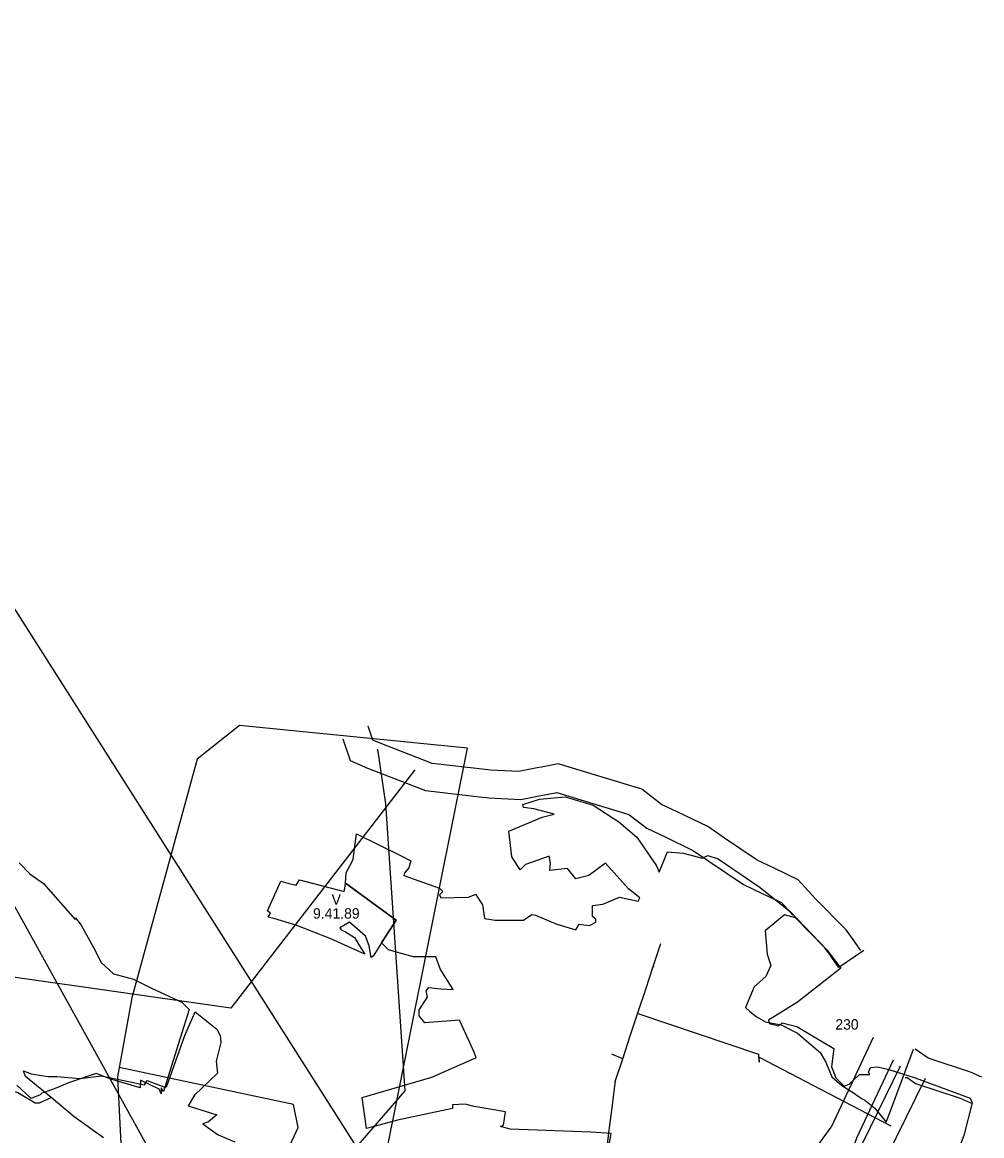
# Model space of a CAD drawing. Extents: x -694504 to -690518, y -983661 to -978958.
# Drawn here: x -691897 to -690518, y -980583 to -978982 of the extents above; entities that cross this region are included whole.
import ezdxf

# ---------------------------------------------------------------- set-up
doc = ezdxf.new("R2010")
doc.units = 0
for name, color, linetype in [('bezpečnostní pásmo', 7, 'Continuous'), ('BPEJ', 7, 'Continuous'), ('chráněné ložiskové území', 7, 'Continuous'), ('lokální biocentra', 7, 'Continuous'), ('nadregionální biokoridor', 7, 'Continuous'), ('Natura 2000', 7, 'Continuous'), ('ochranné pásmo dálkového kabelu', 7, 'Continuous'), ('ochranné pásmo radioreleové trasy', 7, 'Continuous'), ('OP vodního zdroje 2 stupně', 7, 'Continuous'), ('třídy přednosti v ochraně ZP', 7, 'Continuous'), ('vedení NN', 7, 'Continuous'), ('VTL plynovod', 7, 'Continuous')]:
    doc.layers.add(name, color=color, linetype=linetype)

msp = doc.modelspace()

# ---------------------------------------------------------------- linework, layer by layer
at = {"layer": 'bezpečnostní pásmo'}
for points in [[(-690673.7, -980441.7), (-690734.3, -980570.8), (-690734.4, -980570.8), (-691030.9, -980978.4), (-691232.9, -981356.8), (-691374.8, -981727), (-691755.3, -981882.6), (-691867.9, -982087.1), (-691866.5, -982152.1)], [(-691698.8, -981974.2), (-691698.8, -981974.2), (-691689.8, -981958.1), (-691300.2, -981796), (-691146.3, -981397.9), (-690951.9, -981030.3), (-690689.1, -980666.7), (-690682.1, -980670.7), (-690598.6, -980500.1)]]:
    msp.add_lwpolyline(points, dxfattribs=at)
at = {"layer": 'BPEJ'}
for points in [[(-691235.4, -980250.8), (-691232.4, -980270.8), (-691217.4, -980272.8), (-691176.4, -980272.8), (-691164.4, -980264.8), (-691159.4, -980265.8), (-691128.4, -980278.8), (-691101.4, -980286.8), (-691096.4, -980278.8), (-691081.4, -980280.8), (-691072.4, -980275.8), (-691072.4, -980271.8), (-691077.4, -980267.8), (-691077.4, -980251.8), (-691062.4, -980249.8), (-691038.4, -980239.8), (-691011.4, -980245.8), (-691009.4, -980240.8), (-691025.4, -980227.8), (-691058.4, -980190.8), (-691082.4, -980208.8), (-691101.4, -980213.8), (-691113.4, -980198.8), (-691138.4, -980201.8), (-691137.4, -980190.8), (-691139.4, -980180.8), (-691173.4, -980192.8), (-691181.4, -980200.8), (-691193.4, -980181.8), (-691197.4, -980144.8), (-691149.4, -980124.8), (-691132.4, -980120.8), (-691161.4, -980112.8), (-691176.4, -980110.8), (-691177.4, -980106.8), (-691153.4, -980098.8), (-691116.4, -980095.8), (-691076.4, -980107.8), (-691039.4, -980131.8), (-691013.4, -980153.8), (-690985.4, -980194.8), (-690981.4, -980203.8), (-690969.4, -980174.8), (-690946.4, -980176.8), (-690919.4, -980183.8), (-690911.4, -980179.8), (-690896.4, -980184.8), (-690836.4, -980225.8), (-690792.4, -980260.8), (-690740.4, -980315.8), (-690720.4, -980341.8), (-690782.4, -980390.8), (-690824.4, -980416.8), (-690823.4, -980421.8), (-690809.4, -980424.8), (-690804.4, -980420.8), (-690783.4, -980425.8), (-690730.4, -980457.8), (-690733.4, -980483.8), (-690727.4, -980499.8), (-690715.4, -980511.8), (-690708.4, -980508.8), (-690693.4, -980494.8), (-690678.4, -980494.8), (-690680.4, -980491.8), (-690677.4, -980484.8), (-690667.4, -980483.8), (-690651.4, -980487.8), (-690613.4, -980499.8), (-690534.4, -980528.8), (-690531.4, -980535.8), (-690543.4, -980582.8), (-690589.4, -980703.8)], [(-691055.4, -980605.8), (-691050.4, -980579.8), (-691079.4, -980577.8), (-691195.4, -980573.8), (-691209.4, -980569.8), (-691205.4, -980567.8), (-691202.4, -980548.8), (-691247.4, -980540.8), (-691260.4, -980537.8), (-691278.4, -980538.8), (-691278.4, -980543.8), (-691357.4, -980560.8), (-691402.4, -980572.8), (-691408.4, -980527.8), (-691308.4, -980498.8), (-691247.4, -980471.8), (-691244.4, -980470.8), (-691247.4, -980462.8), (-691268.4, -980416.8), (-691318.4, -980420.8), (-691326.4, -980410.8), (-691326.4, -980401.8), (-691314.4, -980383.8), (-691316.4, -980374.8), (-691312.4, -980369.8), (-691295.4, -980371.8), (-691277.4, -980372.8), (-691296.4, -980342.8), (-691302.4, -980325.8), (-691334.4, -980325.8), (-691352.4, -980320.8), (-691370.4, -980315.8), (-691375.4, -980310.8), (-691380.4, -980305.8), (-691359.4, -980272.8), (-691432.4, -980219.8), (-691431.4, -980204.8), (-691421.4, -980185.8), (-691420.4, -980177.8), (-691416.4, -980148.8), (-691353.4, -980179.8), (-691338.4, -980187.8), (-691341.4, -980197.8), (-691347.4, -980204.8), (-691348.4, -980208.8), (-691297.4, -980226.8), (-691292.4, -980231.8), (-691297.4, -980236.8), (-691295.4, -980240.8), (-691255.4, -980239.8), (-691247.4, -980236.8), (-691245.4, -980235.8), (-691235.4, -980250.8)], [(-691780.4, -980585.8), (-691822.4, -980555.8), (-691855.4, -980527.8), (-691892.4, -980497.8), (-691895.4, -980489.8), (-691884.4, -980493.8), (-691860.4, -980497.8), (-691847.4, -980497.8), (-691814.4, -980500.8), (-691783.4, -980496.8), (-691721.4, -980509.8), (-691717.4, -980503.8), (-691691.4, -980513.8), (-691689.4, -980511.8), (-691663.4, -980438.8), (-691648.4, -980404.8), (-691617.4, -980429.8), (-691612.4, -980438.8), (-691611.4, -980448.8), (-691618.4, -980475.8), (-691616.4, -980492.8), (-691649.4, -980524.8), (-691658.4, -980539.8), (-691617.4, -980552.8), (-691629.4, -980562.8)], [(-691944.4, -980516.8), (-691920.4, -980515.8), (-691903.4, -980520.8), (-691878.4, -980535.8), (-691872.4, -980535.8), (-691855.4, -980527.8)], [(-691629.4, -980562.8), (-691637.4, -980565.8), (-691615.4, -980581.8), (-691591.4, -980591.8)]]:
    msp.add_lwpolyline(points, dxfattribs=at)
msp.add_lwpolyline([(-691432.4, -980219.8), (-691359.4, -980272.8), (-691380.4, -980305.8), (-691392.4, -980324.8), (-691395.4, -980326.8), (-691398.4, -980309.8), (-691403.4, -980295.8), (-691426.4, -980275.8), (-691440.4, -980283.8), (-691438.4, -980286.8), (-691432.4, -980289.8), (-691419.4, -980297.8), (-691412.4, -980309.8), (-691404.4, -980321.8), (-691453.4, -980299.8), (-691502.4, -980280.8), (-691535.4, -980270.8), (-691543.4, -980268.8), (-691540.4, -980262.8), (-691544.4, -980259.8), (-691525.4, -980216.8), (-691515.4, -980219.8), (-691503.4, -980222.8), (-691498.4, -980214.8), (-691434.4, -980231.8), (-691433.4, -980226.8), (-691432.4, -980219.8)], close=True, dxfattribs=at)
at = {"layer": 'chráněné ložiskové území'}
msp.add_lwpolyline([(-691332.6, -980056.6), (-691597, -980399.4), (-692068.6, -980332.4), (-692715.6, -979056.8)], dxfattribs=at)
at = {"layer": 'lokální biocentra'}
msp.add_lwpolyline([(-690687.3, -980316.4), (-690722.9, -980340.9), (-690732, -980328.2), (-690735, -980324), (-690743.1, -980312.7), (-690785.6, -980269.6), (-690801, -980265.4), (-690829, -980288.2), (-690826.1, -980322), (-690820.6, -980338.1), (-690828, -980354), (-690844.6, -980369), (-690857.1, -980398.6), (-690851, -980404.2), (-690842.1, -980411.4), (-690828.4, -980419.1), (-690805.8, -980423.4), (-690782.6, -980435.7), (-690749.7, -980463.2), (-690741.6, -980477.1), (-690733.1, -980498.1), (-690718.9, -980510.8), (-690701.9, -980521.4), (-690693.6, -980527.1), (-690689.4, -980530.1), (-690685.6, -980531.9), (-690671.1, -980543.5), (-690655, -980563.5), (-690649, -980547.3), (-690615.9, -980458.4)], dxfattribs=at)
at = {"layer": 'nadregionální biokoridor'}
for points in [[(-690691.3, -980316.4), (-690699.5, -980304.9), (-690702.5, -980300.8), (-690712.4, -980286.9), (-690756.5, -980242.1), (-690781.4, -980214.8), (-690816.1, -980198.4), (-690840.5, -980186.8), (-690887.5, -980155.2), (-690911.5, -980138.4), (-690955.7, -980117.3), (-690978.2, -980106.5), (-691006.2, -980084.8), (-691126.6, -980048.1), (-691150.8, -980052.9), (-691156.9, -980054), (-691183.3, -980059.2), (-691223.9, -980057.1), (-691231.5, -980056.5), (-691307.8, -980047.5), (-691382.6, -980018.7), (-691393.3, -980014.2), (-691399.9, -979994)], [(-691436, -980012.2), (-691425.8, -980043.5), (-691400.9, -980054.5), (-691397, -980056), (-691317.4, -980086.7), (-691235.4, -980096.3), (-691229.6, -980096.8), (-691226.5, -980097), (-691180.5, -980099.4), (-691149.2, -980093.3), (-691143.2, -980092.1), (-691128.7, -980089.3), (-691024.9, -980120.9), (-690999.3, -980140.8), (-690973, -980153.3), (-690931.8, -980173.1), (-690910.1, -980188.2), (-690860.3, -980221.6), (-690833.2, -980234.5), (-690805.7, -980247.6), (-690789, -980265.9)], [(-690517.6, -980499), (-690533.9, -980491.5), (-690594.7, -980471.7), (-690613.2, -980458.5)], [(-690627.7, -980499.4), (-690625, -980499.2), (-690612.9, -980507.8), (-690548.6, -980528.8), (-690531.3, -980536.8)]]:
    msp.add_lwpolyline(points, dxfattribs=at)
at = {"layer": 'Natura 2000'}
msp.add_lwpolyline([(-691901.8, -980190.6), (-691886.4, -980206.2), (-691866.8, -980220.1), (-691821.1, -980272), (-691820.6, -980269.5), (-691812.4, -980280.1), (-691794.5, -980312.2), (-691783.5, -980333.8), (-691765.7, -980350.2), (-691737.2, -980357.9), (-691711.1, -980370.8), (-691700, -980376), (-691698, -980376.9), (-691667.9, -980390.9), (-691657.2, -980401.3), (-691670, -980442.6), (-691684.8, -980490.1), (-691693.9, -980519.4), (-691697.2, -980514.3), (-691697.4, -980522.7), (-691699.5, -980518.2), (-691700.3, -980516.2), (-691726.9, -980503), (-691727.4, -980514.3), (-691769.6, -980501.6), (-691790.9, -980493.6), (-691830.6, -980506.9), (-691847.5, -980514.2), (-691864.2, -980520.3), (-691868.9, -980521.8), (-691871.4, -980524.2), (-691884.1, -980529.3), (-691904.8, -980510.2)], dxfattribs=at)
at = {"layer": 'ochranné pásmo dálkového kabelu'}
msp.add_lwpolyline([(-691386.2, -980026.9), (-691386.2, -980026.9), (-691386.2, -980026.9), (-691386.2, -980026.9), (-691374.9, -980105.5), (-691346.9, -980518.5), (-691469.9, -980660.5), (-691539.9, -980845.5), (-691610.9, -981162.5), (-691809.9, -981375.5), (-691969.9, -981494.5), (-692021.9, -981584.5), (-692040.9, -981697.5), (-692016.9, -981835.5), (-692032.9, -981838.5)], dxfattribs=at)
at = {"layer": 'ochranné pásmo radioreleové trasy'}
for p, q in [((-692444.8, -978981.7), (-690710.2, -981710)), ((-692605.8, -978994.5), (-690996.6, -981898.9))]:
    msp.add_line(p, q, dxfattribs=at)
at = {"layer": 'OP vodního zdroje 2 stupně'}
msp.add_lwpolyline([(-691584.7, -979993.1), (-691645.5, -980041.6), (-691739.8, -980384.6), (-691760.1, -980498.4), (-691750.5, -980690.4), (-691426.7, -980730.4), (-691384.5, -980661.8), (-691268.8, -980085.8), (-691256.8, -980025.6)], close=True, dxfattribs=at)
msp.add_lwpolyline([(-691658.5, -980701.7), (-691533, -980650.1), (-691518.3, -980609.5), (-691500.2, -980571.2), (-691507.1, -980538.1), (-691757.6, -980484.7)], dxfattribs=at)
at = {"layer": 'vedení NN'}
for points in [[(-690989.8, -980339.5), (-690979.4, -980307.8), (-690978.9, -980306.6)], [(-691012, -980406.2), (-691000.6, -980372), (-690989.8, -980339.5)], [(-690988.7, -980339.9), (-690989.8, -980339.5)], [(-691033.8, -980472.4), (-691022.9, -980439.2), (-691012, -980406.2)], [(-691012.1, -980407.4), (-691012, -980406.2)], [(-691012.1, -980407.4), (-691011.9, -980407.4), (-690838.4, -980465.8), (-690837.9, -980476.5), (-690837.4, -980476.6)], [(-691033.8, -980472.4), (-691049.6, -980465.7)], [(-690837.4, -980476.6), (-690837, -980476.8), (-690837.4, -980470.1), (-690648.5, -980568.7)], [(-691044.2, -980503.7), (-691033.8, -980472.4)], [(-691078.6, -980765.7), (-691078.7, -980765.5), (-691077.6, -980765), (-691073, -980725.4), (-691067.9, -980687.6), (-691063.1, -980651.5), (-691057.7, -980612), (-691053.1, -980575.1), (-691048.7, -980539.2), (-691044.2, -980503.7)], [(-691044.5, -980505), (-691044.2, -980503.7)]]:
    msp.add_lwpolyline(points, dxfattribs=at)
at = {"layer": 'VTL plynovod'}
for points in [[(-691827.1, -982121.4), (-691827.6, -982097), (-691727.1, -981914.3), (-691343.6, -981757.4), (-691196.4, -981373.4), (-690997, -980999.7), (-690711.8, -980607.8), (-690699.3, -980614.9), (-690634.5, -980482.5)], [(-691814.1, -982124.6), (-691815.4, -982100.9), (-691717.9, -981926.4), (-691331.3, -981765.6), (-691182.8, -981381.3), (-690986, -981009.1), (-690713.3, -980632), (-690697.3, -980585.9), (-690644.7, -980474.1)]]:
    msp.add_lwpolyline(points, dxfattribs=at)

# ---------------------------------------------------------------- texts
at = {"layer": 'třídy přednosti v ochraně ZP'}
for s, p in [('V', (-691452.3, -980250.8)), ('9.41.89', (-691479, -980270.8)), ('230', (-690728.1, -980430.4))]:
    msp.add_text(s, height=15, dxfattribs=at).set_placement(p)

doc.saveas('drawing.dxf')
